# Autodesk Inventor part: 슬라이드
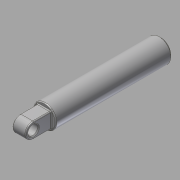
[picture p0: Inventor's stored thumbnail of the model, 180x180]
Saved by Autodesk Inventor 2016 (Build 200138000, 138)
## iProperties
Created: 2016-02
Part Number: 슬라이드
Material: 강철, 연강
Document SubType Name: Modeling
Designer: test
Density: 1 g/cm^3
Appearance: 강철
Author: test
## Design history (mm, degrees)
sketch "스케치2"
  geometry: C1 r 6 at (0, 0); 1 further point
  constraints: 1 centre point, 1 coincident
  dimensions: "d0" = 12 diameter of C1
extrude "돌출1" new body sketch "스케치2" distance "d1" = 60; taper "d2" = 0 deg
hole "구멍1" diameter "d5" = 5.917; stored, may be unused: countersink angle "d9" = 90 deg, drill point angle "d11" = 118 deg; dims "d3" = 10, "d4" = 10, "d6" = 10, "d7" = 4, "d8" = 2, "d10" = 12
chamfer "모따기1" distance "d12" = 1; stored, may be unused: second distance "d13" = 2, angle "d14" = 45 deg
sketch "스케치3"
  geometry: L1 (0, 6)-(0, -6) reference; L2 (0, 4)-(-9, 4); L3 (-9, -4)-(0, -4); L4 (0, -4)-(0, 4); C1 r 2.5 at (-9, 0); A1 r 4 centre (-9, 0) between (-9, 4) and (-9, -4); 2 further points
  constraints: 6 end point, 2 centre point, 2 point on circle, 2 tangent, 1 coincident, 1 horizontal, 1 horizontal alignment, 1 midpoint, 1 parallel, 1 point on line, 1 vertical
  dimensions: "d15" = 13 dimension on A1 L1; "d16" = 8 distance between parallel lines of L3 L2; "d17" = 5 diameter of C1
extrude "돌출2" join sketch "스케치3" stored distance "d18" = 7; taper "d19" = 0 deg
chamfer "모따기2" distance "d20" = 0.5; stored, may be unused: second distance "d21" = 2, angle "d22" = 45 deg
fillet "모깎기1" dims "d23" = 0.5
fillet "모깎기2" dims "d24" = 0.5
fillet "모깎기3" dims "d25" = 0.5
node "솔리드1"
